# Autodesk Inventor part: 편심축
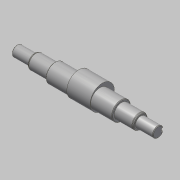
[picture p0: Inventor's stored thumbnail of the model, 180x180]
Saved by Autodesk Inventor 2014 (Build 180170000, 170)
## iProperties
Created: 2015-10
Part Number: 편심축
Document SubType Name: Modeling
Designer: mdu
Density: 7.86 g/cm^3
Material: 강철, 연강
Mass: 1267.06 g
Surface Area: 239.297 cm^2
Volume: 161.203 cm^3
Appearance: 강철
Author: mdu
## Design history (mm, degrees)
sketch "스케치1"
  geometry: L1 (-20.5, -41.331)-(-20.5, 32.669) reference; L2 (7.5, -30.031)-(7.5, 21.369) reference; L3 (135.5, -30.331)-(135.5, 21.669) reference; L4 (121.5, 21.369)-(121.5, -30.031) reference; L5 (184.5, -4.331)-(-57.5, -4.331); L6 (184.5, -4.331)-(184.5, 4.669); L7 (154.5, 8.169)-(121.5, 8.169); L8 (121.5, 8.169)-(121.5, 11.669); L9 (121.5, 11.669)-(7.5, 11.669); L10 (7.5, 11.669)-(7.5, 8.169); L11 (7.5, 8.169)-(-27.5, 8.169); L12 (-27.5, 8.169)-(-27.5, 4.669); L13 (-27.5, 4.669)-(-57.5, 4.669); L14 (-57.5, 4.669)-(-57.5, -4.331); L15 (154.5, 8.169)-(154.5, 4.669); L16 (154.5, 4.669)-(184.5, 4.669); C1 r 32.5 at (64.5, -4.331) reference; 1 further point
  constraints: 24 end point, 8 perpendicular, 5 point on line, 3 parallel, 2 collinear
  dimensions: "d1" = 25 diameter of L11 L5; "d2" = 32 diameter of L9 L5; "d3" = 18 diameter of L13 L5; "d4" = 35 distance of L10.end L11.end; "d5" = 30 distance of L12.end L13.end; "d15" = 33 distance of L7.start L7.end; "d26" = 30 distance of L15.end L6.end
revolve "회전1" sketch "스케치1" stored, may be unused: angle "d6" = 90 deg
node "작업 평면1"
sketch "스케치2"
  geometry: C1 r 16 at (0, 0) reference; C2 r 20.75 at (0, 4)
  constraints: 1 centre point, 1 vertical alignment
  dimensions: "d34" = 4 distance of C2.centre C1.centre; "d35" = 41.5 diameter of C2
extrude "돌출1" join sketch "스케치2" stored distance "d9" = 40; taper "d10" = 0 deg
chamfer "모따기1" distance "d11" = 1; stored, may be unused: second distance "d12" = 2, angle "d13" = 45 deg
node "작업 평면2"
sketch "스케치3"
  geometry: L1 (-15, -8)-(-15, 8) reference; L2 (-15, 3)-(0, 3); L3 (0, -3)-(-15, -3); A1 r 3 centre (0, 0) between (0, -3) and (0, 3); 2 further points
  constraints: 4 end point, 2 perpendicular, 2 point on circle, 2 point on line, 2 tangent, 1 centre point, 1 horizontal alignment, 1 midpoint
  dimensions: "d16" = 18 dimension on A1 L1; "d17" = 6 distance between parallel lines of L3 L2
extrude "돌출2" cut sketch "스케치3" distance "d18" = 3.5; taper "d19" = 0 deg
node "작업 평면3"
chamfer "모따기2" distance "d36" = 2.2; stored, may be unused: second distance "d37" = 2, angle "d38" = 30 deg
chamfer "모따기3" distance "d39" = 2.2; stored, may be unused: second distance "d40" = 2, angle "d41" = 30 deg
fillet "모깎기1" dims "d42" = 1, "d43" = 2
fillet "모깎기2" dims "d44" = 1, "d45" = 2
node "솔리드1"
mirror "대칭1"
node "참조1"
node "참조2"
node "참조3"
node "참조4"
node "참조5"
other parameters: "d30" = 35
